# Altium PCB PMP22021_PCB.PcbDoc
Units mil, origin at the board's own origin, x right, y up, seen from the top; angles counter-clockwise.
Board outline 2283.46 x 1181.1 mil, 2 copper layers (Top Layer, Bottom Layer), stack 62 mil thick; 38 components, 23 nets, 108 pads, 31 vias.
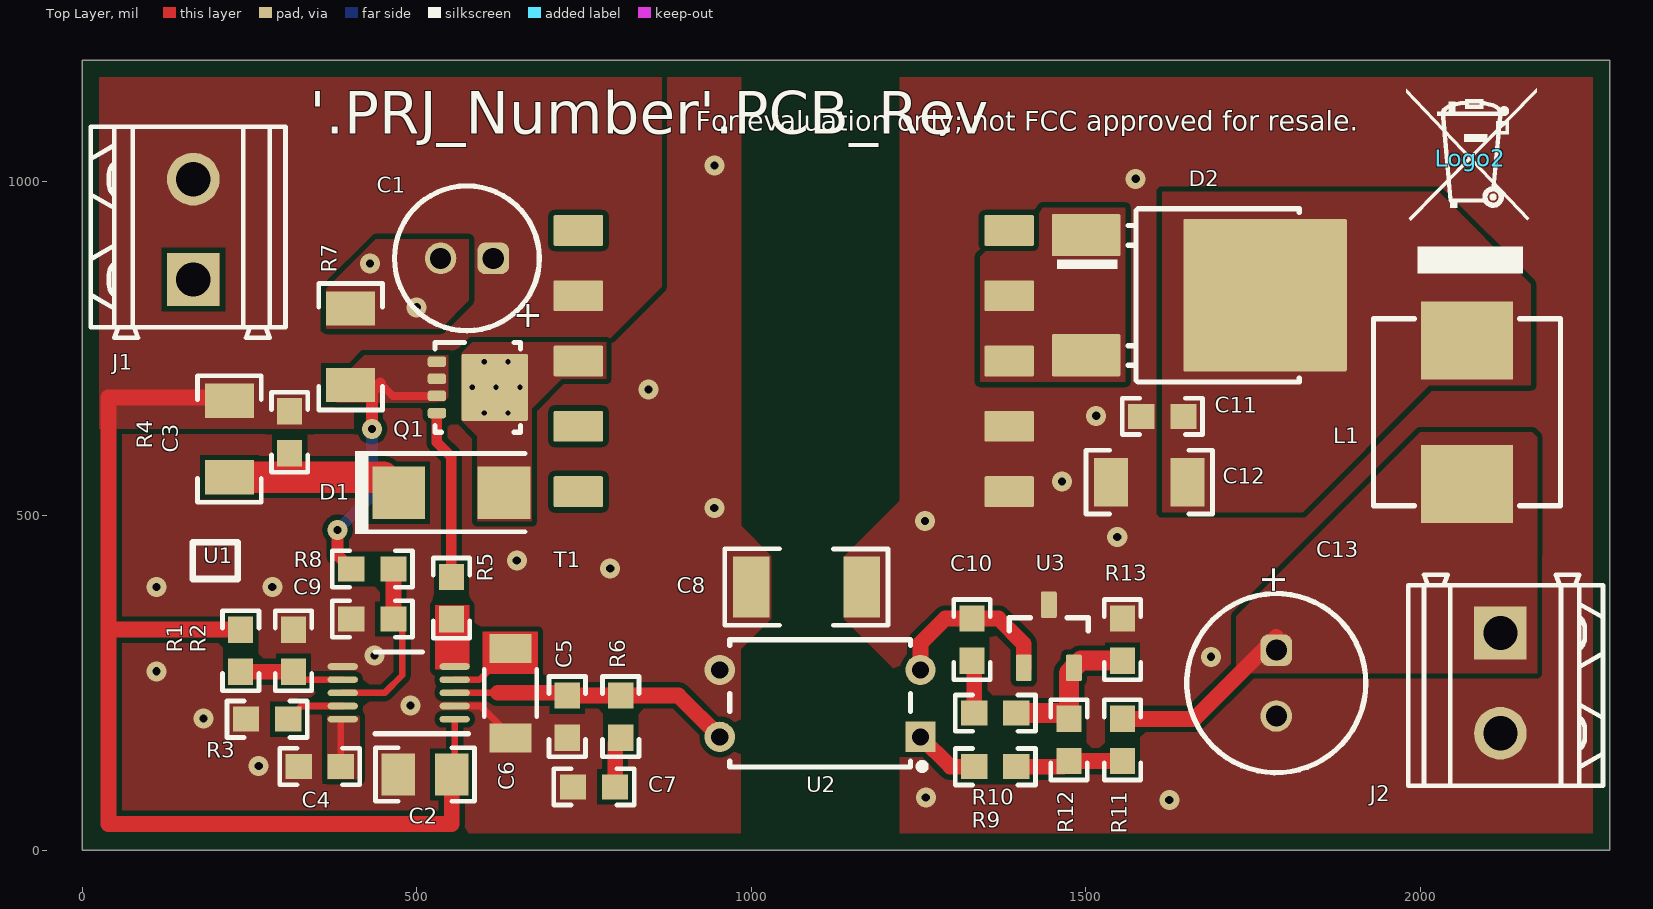
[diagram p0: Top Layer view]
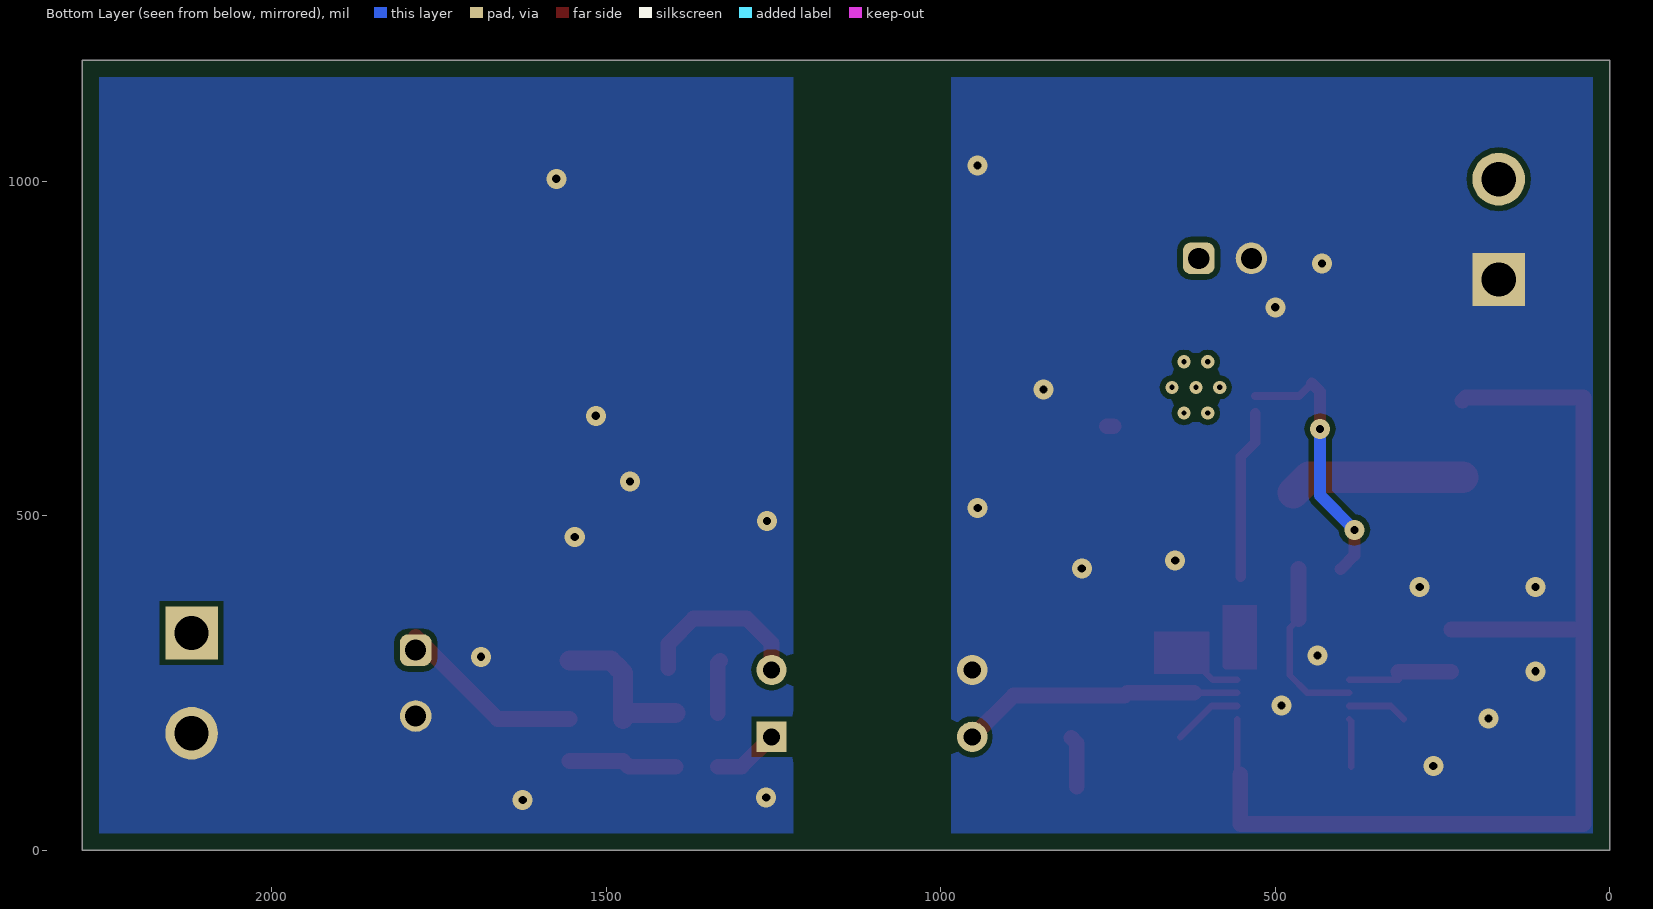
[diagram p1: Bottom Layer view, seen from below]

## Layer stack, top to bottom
Top Solder: solder mask 0.4, Solder Resist, Dk 3.5
Top Layer: signal copper 1.4
Dielectric1: core 59.2, FR-4, Dk 4.8
Bottom Layer: signal copper 1.4
Bottom Solder: solder mask 0.4, Solder Resist, Dk 3.5

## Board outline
0,0 2283.46,0 2283.46,1181.1 0,1181.1

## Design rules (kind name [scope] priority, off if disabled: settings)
AcuteAngle [All] p1: minimum=4.50000000000000E+0001 checktracksonly=FALSE
AssemblyTestPointUsage [All] p1: valid=2
BoardOutlineClearance BoardOutlineClearance_MountingHoles [OnCopper and InComponentClass('Mounting Holes')] p1: gap=25 ignorepadtopadclearanceinfootprint=FALSE
BoardOutlineClearance BoardOutlineClearance_Poly [OnCopper and InPoly] p2: gap=25 ignorepadtopadclearanceinfootprint=FALSE
BoardOutlineClearance [OnCopper and Not InComponentClass('Logo') and not InComponentClass('FiducialMark') and not InRegion(1000,500,4000,800)] p3: gap=25 ignorepadtopadclearanceinfootprint=FALSE
Clearance Clearance_Keepouts [((IsTrack Or IsArc) And Not InPoly) And IsFree and IsKeepOut vs ((IsTrack Or IsArc) And Not InPoly) And IsFree and IsKeepOut] p1: gap=0 ignorepadtopadclearanceinfootprint=FALSE
Clearance Clearance_Poly [InPolygon] p2: gap=8 ignorepadtopadclearanceinfootprint=FALSE except(0: Arc-Hole Track-Hole SMDPad-Hole THPad-Hole Via-Hole Fill-Hole Poly-Hole Region-Hole Text-Hole)
Clearance [All] p3: gap=7.87 ignorepadtopadclearanceinfootprint=FALSE except(0: Arc-Hole Track-Hole SMDPad-Hole THPad-Hole Via-Hole Fill-Hole Poly-Hole Region-Hole Text-Hole)
ComponentClearance ComponentClearance_MountingHoles_FiducialMarks [InComponentClass('Mounting Holes') vs InComponentClass('FiducialMark')] p1: gap=50 collisioncheckmode=3 verticalgap=10 showdistances=FALSE
ComponentClearance ComponentClearance_Shunt [InComponentClass('Header') vs InComponentClass('Shunt')] p2: gap=0 collisioncheckmode=3 verticalgap=0 showdistances=FALSE
ComponentClearance ComponentClearance_Logo [InComponentClass('Logo')] p3: gap=50 collisioncheckmode=3 verticalgap=10 showdistances=FALSE
ComponentClearance ComponentClearance_ScrewToNut [(HasFootprint('NY PMS 440 0025 PH')) vs (HasFootprint('Keystone_1902C'))] p4: gap=5 collisioncheckmode=3 verticalgap=10 showdistances=FALSE
ComponentClearance ComponentClearance_MountingHoles [InComponentClass('Mounting Holes')] p5: gap=250 collisioncheckmode=3 verticalgap=100000 showdistances=FALSE
ComponentClearance ComponentClearance_SmallPassives [HasFootprint('0201*') or HasFootprint('0402*') or HasFootprint('0508') or HasFootprint('0603*') or HasFootprint('0612') or HasFootprint('0805*') or HasFootprint('0815*') or HasFootprint('0830*') or HasFootprint('1206*') or HasFootprint('1210*') or HasFootprint('1808*') or HasFootprint('1812*') or HasFootprint('1825*') or HasFootprint('2010*') or HasFootprint('2220*') or HasFootprint('2225*') or HasFootprint('2512*') or HasFootprint('2728*') or HasFootprint('3518*') vs HasFootprint('0201*') or HasFootprint('0402*') or HasFootprint('0508') or HasFootprint('0603*') or HasFootprint('0612') or HasFootprint('0805*') or HasFootprint('0815*') or HasFootprint('0830*') or HasFootprint('1206*') or HasFootprint('1210*') or HasFootprint('1808*') or HasFootprint('1812*') or HasFootprint('1825*') or HasFootprint('2010*') or HasFootprint('2220*') or HasFootprint('2225*') or HasFootprint('2512*') or HasFootprint('2728*') or HasFootprint('3518*')] p6: gap=14.96 collisioncheckmode=3 verticalgap=10 showdistances=FALSE
ComponentClearance ComponentClearance_THtoSMT [IsThruComponent vs IsSMTComponent] p7: gap=15 collisioncheckmode=3 verticalgap=30 showdistances=FALSE
ComponentClearance ComponentClearance_THtoTH [IsThruComponent vs IsThruComponent] p8: gap=15 collisioncheckmode=3 verticalgap=30 showdistances=FALSE
ComponentClearance [All] p9: gap=15 collisioncheckmode=3 verticalgap=10 showdistances=FALSE
DiffPairsRouting [All] p1: maxlimit=100 minlimit=10 mostfreqgap=10 toplayer_minwidth=15 toplayer_maxwidth=15 toplayer_prefwidth=15 bottomlayer_minwidth=15 bottomlayer_maxwidth=15 bottomlayer_prefwidth=15 maxuncoupledlength=1000
FabricationTestPointUsage TestPointUsage [All] p1: valid=2 allowmultiple=FALSE
FabricationTestpoint Testpoint [All] p1: side=3 testpointundercomponent=TRUE minsize=40 maxsize=100 preferedsize=60 minholesize=0 maxholesize=40 preferedholesize=32 testpointgrid=1 allowsidetop=TRUE allowsidebottom=TRUE usegrid=TRUE gridtolerance=0.01
FanoutControl Fanout_LCC [IsLCC] p1: bgadir=Out bgaviamode=Centered fanoutstyle=Auto fanoutdirection=Alternating viagrid=1 // Fanout_LCC (Default Rule)
FanoutControl Fanout_BGA [IsBGA] p2: bgadir=Out bgaviamode=Centered fanoutstyle=Auto fanoutdirection=Alternating viagrid=1 // Fanout_BGA (Default Rule)
FanoutControl Fanout_Default [All] p4: bgadir=Out bgaviamode=Centered fanoutstyle=Auto fanoutdirection=Alternating viagrid=1 // Fanout_Default (Default Rule)
FanoutControl Fanout_Small [(CompPinCount < 5)] p5: bgadir=Out bgaviamode=Centered fanoutstyle=Auto fanoutdirection=OutThenIn viagrid=1 // Fanout_Small (Default Rule)
HoleSize [All] p1: absolutevalues=TRUE maxlimit=251 minlimit=7.87 maxpercent=80.000 minpercent=20.000
MinimumAnnularRing MinimumAnnularRing_ThermalPadVias [IsVia and InAnyComponent] p1: minimumring=5.91
MinimumAnnularRing [All] p2: minimumring=8
MinimumSolderMaskSliver MinimumSolderMaskSliver_Logo [InComponentClass('Logo') vs InComponentClass('Logo')] p1: minsoldermaskwidth=0.7
MinimumSolderMaskSliver [All] p2: minsoldermaskwidth=3.94
PlaneConnect [All] p1: planeconnectstyle=Direct reliefexpansion=10 reliefentries=4 reliefconductorwidth=10 reliefairgap=10
PolygonConnect [All] p1: connectstyle=Direct reliefconductorwidth=10 reliefentries=4 polygonreliefangle="90 Angle" airgapwidth=10
RoutingVias ThermalPadVias [IsVia and InAnyComponent] p1: holewidth=7.87 width=19.68 viastyle="Through Hole" minholewidth=7.87 minwidth=19.68 maxholewidth=12.99 maxwidth=23.62
RoutingVias [All] p2: holewidth=16 width=34 viastyle="Through Hole" minholewidth=7.87 minwidth=26 maxholewidth=40 maxwidth=65
SilkToBoardRegionClearance [Not ((IsComment or IsDesignator) And (Hide <> 'False')) and not InRegion(1000,500,4000,800)] p1:
SilkToSilkClearance SilkToSilkClearance_Pb-FreeLogo [(HasFootprint('Pb-Free_Overlay_Medium') OR HasFootprint('Pb-Free_Overlay_Small')) vs (HasFootprint('Pb-Free_Overlay_Medium') OR HasFootprint('Pb-Free_Overlay_Small'))] p1: silktosilkclearance=0
SilkToSilkClearance [All] p2: silktosilkclearance=4
SilkToSolderMaskClearance SilkToComponentPadClearance [IsPad and InAnycomponent] p1: minsilkscreentomaskgap=5 clearancetoexposedcopper=TRUE
SilkToSolderMaskClearance "Silk to Solder Mask Opening" [All] p2: minsilkscreentomaskgap=4 clearancetoexposedcopper=FALSE
SolderMaskExpansion [All] p1: expansion=1.97
Width [All] p1: maxlimit=100 minlimit=6 preferedwidth=10 checkconnectedcopper=TRUE
15 further rules are at their usual default settings.

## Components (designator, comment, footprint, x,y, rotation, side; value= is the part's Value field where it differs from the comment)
C1 "860020472003" WCAP-ATG5_500x1100 575,885 r180 top value=10uF
C2 "GRM219R71E105KA88D" 0805_HV 512.44,113.39 r180 top value=1uF
C3 "GRM188R71H273KA61D" 0603 310,625 r270 top value=0.027uF
C4 "GCM188R71H103KA37D" 0603 354.96,125.2 r0 top value=0.01uF
C5 "GRM188R71E104KA01D" 0603 725,200 r90 top value=0.1uF
C6 "GRM31CR71E106KA12L" 1206_180 640,235 r270 top value=10uF
C7 "GRM188R71E105KA12D" 0603 765,95 r180 top value=1uF
C8 "GR442QR73D102KW01L" 1808 1082.68,393.7 r180 top value=1000pF
C9 "06033C101KAT2A" 0603 433.7,345.67 r0 top value=100pF
C10 "GRM188R71C333KA01D" 0603 1330,315 r270 top value=0.033uF
C11 "GRM188R71E105KA12D" 0603 1614.8,648.82 r180 top value=1uF
C12 "C3216X7R1A106K085AC" 1206 1595.12,550.39 r180 top value=10uF
C13 "860010273010" WCAP-ATG8_630x1100 1785,250 r270 top value=330uF
D1 "MURA110T3G" SMA 551.81,534.65 r0 top value=100V
D2 "MBRD1035CTLT4G" DPAK 1634.49,829.92 r0 top value=35V
J1 "691214310002" Wurth_691214310002 165.98,928.35 r90 top
J2 "691214310002" Wurth_691214310002 2120,250 r270 top
L1 "74437349022" WE-LHMI_7050 2070,655 r270 top value=2.2uH
Logo1 "FCC disclaimer" FCC_disclaimer 2870,1255 r0 top
Logo2 "WEEE logo" WEEE_Minimum 2075,1035 r0 top
Q1 "CSD18543Q3A" DNH0008A 591.18,692.13 r0 top value=60V
R1 "CRCW060321K0FKEA" 0603 236.85,298.43 r90 top value=21.0k
R2 "CRCW06034K87FKEA" 0603 315.59,298.43 r270 top value=4.87k
R3 "CRCW060384K5FKEA" 0603 276.22,196.06 r180 top value=84.5k
R4 "CRCW12062K00JNEA" 1206 220,615 r90 top value=2.0k
R5 "CRCW06032R20JNEA" 0603 551.81,377.17 r90 top value=2.2
R6 "CRCW0603499RFKEA" 0603 805,200 r90 top value=499
R7 "CSR1206FKR300" 1206 401.1,752.8 r270 top value=0.3
R8 "CRCW0603200RJNEA" 0603 433.7,420.47 r0 top value=200
R9 "CRCW0603511RFKEA" 0603 1365,125 r0 top value=511
R10 "CRCW06034K42FKEA" 0603 1365,205 r0 top value=4.42k
R11 "CRCW06030000Z0EA" 0603 1555,165 r90 top value=0
R12 "CRCW060314K3FKEA" 0603 1475,165 r270 top value=14.3k
R13 "CRCW060342K2FKEA" 0603 1555,315 r270 top value=42.2k
T1 "750310035" FP-750310035_SMT_17MM75_13MM46-MFG 1063.62,731.5 r0 top
U1 "LM5022QDGSRQ1" DGS0010A_L 473.07,235.43 r180 top
U2 "VO618A-3" DIP-4 1102.99,219.69 r180 top
U3 "ATL431AIDBZR" DBZ0003A_N 1445,320 r90 top

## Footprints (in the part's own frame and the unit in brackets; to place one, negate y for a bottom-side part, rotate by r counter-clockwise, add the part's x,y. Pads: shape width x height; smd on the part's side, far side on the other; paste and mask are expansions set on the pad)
0603 [mm] "0603 from SM-752 data"
  rect 1x0.95 smd: 1(-0.8,0) 2(0.8,0)
  silkscreen extent -1.52,-0.69 1.52,0.69, body extent -0.87,-0.47 0.87,0.47, height 1
0805_HV [mil] "0805 with 30mil clearance between pads"
  rect 50x63 smd: 1(-40,0) 2(40,0)
  silkscreen extent -74,-40 74,40, body extent -43,-29 43,29, height 57
1206 [mm] "1206 from SM-752 data"
  rect 1.3x1.85 smd: 1(-1.45,0) 2(1.45,0)
  silkscreen extent -2.4,-1.21 2.4,1.21, body extent -1.7,-0.9 1.7,0.9, height 1.35
1206_180 [mm] "1206_180"
  rect 1.1x1.6 smd: 1(-1.7,0) 2(1.7,0)
  silkscreen extent -0.9,-1 0.9,1, body extent -1.75,-0.95 1.75,0.95, height 1.8
1808 [mm] "Chip Capacitor, Body 4.6x2.0mm, IPC Medium Density"
  rect 1.4x2.3 smd: 1(-2.1,0) 2(2.1,0)
  silkscreen extent -3.1,-1.45 3.1,1.45, body extent -2.47,-1.2 2.47,1.2, height 2.03
DBZ0003A_N [mm] "SOT23, 3-Leads, Body 2.9x1.3mm, Pitch 0.95mm, Lead Span 2.4mm, IPC Medium Density"
  rrect17% 1x0.6 smd: 1(-1.2,0.95) 2(-1.2,-0.95) 3(1.2,0)
  silkscreen extent 0.2,-1.5 0.7,1.5, body extent -1.26,-1.46 1.26,1.46, height 0.98
DGS0010A_L [mm] "TSSOP, 10-Leads, Body 3x3mm, Pitch 0.5mm, IPC High Density"
  oval 1.15x0.25 smd: 1(-2.125,1) 2(-2.125,0.5) 3(-2.125,0) 4(-2.125,-0.5) 5(-2.125,-1) 6(2.125,-1) 7(2.125,-0.5) 8(2.125,0) 9(2.125,0.5) 10(2.125,1)
  silkscreen extent -2.65,-1.55 0.9,1.55, body extent -2.45,-1.5 2.45,1.5, height 0.96
DIP-4 [mm] "DIP, 4-Leads, Body 6.86x4.83mm, Pitch 2.54mm"
  rect 1.15x1.15 hole 0.65: 1(-3.81,1.27)
  round 1.15 hole 0.65: 2(-3.81,-1.27) 3(3.81,-1.27) 4(3.81,1.27)
  silkscreen extent -4,-2.41 3.43,2.52, body extent -4.02,-2.41 4.02,2.41, height 5.59
DNH0008A [mm] "8 pin VSONP, 0.65 mm pitch"
  rrect50% 0.7x0.4 smd paste-0.05 mask-0.05: 1(-1.55,0.975) 2(-1.55,0.325) 3(-1.55,-0.325) 4(-1.55,-0.975) 5(1.55,-0.975) 6(1.55,-0.325) 7(1.55,0.325) 8(1.55,0.975)
  rrect14% 0.705x1.125 on Top Paste: 9(-0.208,-0.663) 9(-0.208,0.662) 9(0.697,-0.663) 9(0.697,0.662)
  rrect6% 1.775x2.45 on Top Solder: 9(0.327,0)
  rrect4% 2.51x2.55 smd paste-1.5 mask-1.5: 9(0.645,0)
  rect 0.5x0.3 on Top Solder: 9(1.175,-0.975) 9(1.175,-0.325) 9(1.175,0.325) 9(1.175,0.975)
  silkscreen extent -1.62,-1.7 1.62,1.7, body extent -1.65,-1.65 1.65,1.66, height 0.91
DPAK [mm] "D-PAK, 3-Pads, Body 6.22x6.73mm (max), TO-252AA using nominal STEP model"
  rrect6% 2.6x1.6 smd: 1(-3.4,2.28) 3(-3.4,-2.28)
  rrect2% 6.2x5.8 smd paste-2.9: 4(3.4,0)
  silkscreen extent -4.5,-3.3 4.7,3.28, body extent -3.86,-3.29 5.84,3.29, height 2.48
FCC_disclaimer [mil]
FP-750310035_SMT_17MM75_13MM46-MFG [mm]
  rrect9% 1.88x1.17 smd paste+0 mask+0: 1(-8.18,-4.96) 2(-8.18,-2.48) 3(-8.18,0) 4(-8.18,2.48) 5(-8.18,4.96) 6(8.18,4.96) 7(8.18,2.48) 8(8.18,0) 9(8.18,-2.48) 10(8.18,-4.96)
  body extent -9.22,-6.83 9.22,6.83, height 0.25
SMA [mm] "Molded Diode, 2-Leads, Body 4.3x2.6mm, IPC Medium Density, based on OnSemi component dimensions and land pattern"
  rect 2x2 smd: 1(-2,0) 2(2,0)
  silkscreen extent -3.66,-1.57 2.79,1.57, body extent -2.6,-1.3 2.6,1.3, height 2.42
WCAP-ATG5_500x1100 [mm] "TH, 2-Leads, Dia 5mm, Pin Spacing 2mm"
  rrect50% 1.2x1.2 hole 0.8: 1(-1,0)
  round 1.2 hole 0.8: 2(1,0)
  silkscreen extent -2.75,-2.75 2.75,2.75, body extent -2.5,-2.5 2.49,2.5, height 11.11
WCAP-ATG8_630x1100 [mm] "TH, 2-Leads, Dia 6.3mm, Pin Spacing 2.5mm"
  rrect50% 1.2x1.2 hole 0.8: 1(-1.25,0)
  round 1.2 hole 0.8: 2(1.25,0)
  silkscreen extent -3.4,-3.4 3.4,3.4, body extent -3.15,-3.15 3.14,3.15, height 11.11
WE-LHMI_7050 [mm] "Wurth"
  rect 2.95x3.5 smd: 1(-2.725,0) 2(2.725,0)
  silkscreen extent -3.55,-3.55 3.55,3.55, body extent -3.8,-3.45 3.8,3.45, height 5
WEEE_Minimum [mil] "WEEElie bin"
  silkscreen extent -95,-172 99,104
Wurth_691214310002 [mm] "WE"
  rect 2x2 hole 1.3: 1(-1.905,0)
  round 2 hole 1.3: 2(1.905,0)
  silkscreen extent -4.12,-3.5 3.9,3.9, body extent -4.12,-3.5 3.9,3.9, height 8.52

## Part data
C1: library part CMP-0860288-1, "CAP, AL, 10 µF, 25 V, +/- 20%, TH", Cap_Case=5x11mm, Manufacturer="Wurth Elektronik", Tolerance_%=20%, Value2=25V, ValueDisplayed=10µF
C2: library part CMP-0008217-2, "CAP, CERM, 1 uF, 25 V, +/- 10%, X7R, 0805", Cap_Case=0805, Manufacturer=MuRata, Supplier Part Number 1=GRM219R71E105KA88D-ND, TempCo=X7R, Tolerance_%=10%, Value1=Unknown, Value2=25V, ValueDisplayed=1uF
C3: library part CMP-0007448-4, "CAP, CERM, 0.027 uF, 50 V, +/- 10%, X7R, 0603", Cap_Case=0603, Manufacturer=MuRata, Supplier Part Number 1=81-GRM188R71H273KA61, TempCo=X7R, Tolerance_%=10%, Value1=Unknown, Value2=50V, ValueDisplayed=0.027uF
C4: library part CMP-0007143-4, "CAP, CERM, 0.01 uF, 50 V, +/- 10%, X7R, AEC-Q200 Grade 1, 0603", Cap_Case=0603, Manufacturer=MuRata, Supplier Part Number 1=490-4778-1-ND, TempCo=X7R, Tolerance_%=10%, Value1=Unknown, Value2=50V, ValueDisplayed=0.01uF
C5: library part CMP-0007404-4, "CAP, CERM, 0.1 uF, 25 V, +/- 10%, X7R, 0603", Cap_Case=0603, Manufacturer=MuRata, Supplier Part Number 1=490-1524-1-ND, TempCo=X7R, Tolerance_%=10%, Value1=Unknown, Value2=25V, ValueDisplayed=0.1uF
C6: library part CMP-0008965-2, "CAP, CERM, 10 uF, 25 V, +/- 10%, X7R, 1206", Cap_Case=2220, Manufacturer=MuRata, Supplier Part Number 1=81-GRM31CR71E106KA12, TempCo=X7R, Tolerance_%=10%, Value1=Unknown, Value2=25V, ValueDisplayed=10uF
C7 C11: library part CMP-0007405-4, "CAP, CERM, 1 uF, 25 V, +/- 10%, X7R, 0603", Cap_Case=0603, Manufacturer=MuRata, Supplier Part Number 1=490-5307-1-ND, TempCo=X7R, Tolerance_%=10%, Value1=Unknown, Value2=25V, ValueDisplayed=1uF
C8: library part CMP-0009436-2, "CAP, CERM, 1000 pF, 2000 V, +/- 10%, X7R, 1808", Cap_Case=1808, Manufacturer=MuRata, Supplier Part Number 1=490-8145-1-ND, TempCo=X7R, Tolerance_%=10%, Value1=Unknown, Value2=2000V, ValueDisplayed=1000pF
C9: library part CMP-0006751-4, "CAP, CERM, 100 pF, 25 V, +/- 10%, X7R, 0603", Cap_Case=0603, Manufacturer=AVX, Supplier Part Number 1=55J3899, TempCo=X7R, Tolerance_%=10%, Value1=Unknown, Value2=25V, ValueDisplayed=100pF
C10: library part CMP-0007392-5, "CAP, CERM, 0.033 uF, 16 V, +/- 10%, X7R, 0603", Cap_Case=0603, Manufacturer=MuRata, Supplier Part Number 1=490-1528-1-ND, TempCo=X7R, Tolerance_%=10%, Value1=Unknown, Value2=16V, ValueDisplayed=0.033uF
C12: library part CMP-0008687-2, "CAP, CERM, 10 uF, 10 V, +/- 10%, X7R, 1206", Cap_Case=1206, Manufacturer=TDK, Supplier Part Number 1=445-14793-1-ND, TempCo=X7R, Tolerance_%=10%, Value1="0.002454 ohm", Value2=10V, ValueDisplayed=10uF
C13: library part CMP-0860287-1, "CAP, AL, 330 µF, 10 V, +/- 20%, TH", Cap_Case=6.3x11mm, Manufacturer="Wurth Elektronik", Tolerance_%=20%, Value2=10V, ValueDisplayed=330µF
D1: library part CMP-0029196-2, "Diode, Ultrafast, 100 V, 2 A, SMA", Manufacturer="ON Semiconductor", Value1=2A, Value2=V
D2: library part CMP-0028474-1, "Diode, Schottky, 35 V, 10 A, DPAK", Manufacturer="ON Semiconductor", Supplier Part Number 1=MBRD1035CTLT4GOSCT-ND, Value1=10A, Value2=0.56V
J1 J2: library part CMP-0054822-2, "Terminal Block, 2x1, 3.81mm, 24-16 AWG, 10A, 300VAC, TH", Manufacturer="Wurth Elektronik"
L1: library part CMP-0064106-1, "Inductor, Shielded Drum Core, Powdered Iron, 2.2 uH, 7.5 A, 0.0112 ohm, SMD", Manufacturer="Wurth Elektronik", Supplier Part Number 1=732-3352-1-ND, Value1="0.0112 ohm", Value2=7.5A, ValueDisplayed=2.2uH
Logo1: library part CMP-0074847-1, "FCC_disclaimer"
Logo2: library part CMP-0074769-1
Q1: library part CMP-0000826-1, "MOSFET, N-CH, 60 V, 35 A, DNH0008A (VSONP-8)", Alternate Manufacturer=None, Manufacturer="Texas Instruments", Supplier Part Number 1=CSD18543Q3A-ND, Value1=0.01, Value2="11.1 nC"
R1: library part CMP-0022212-4, "RES, 21.0 k, 1%, 0.1 W, AEC-Q200 Grade 0, 0603", Manufacturer=Vishay-Dale, Power_W=100mW, Supplier Part Number 1=541-21.0KHCT-ND, TempCo="100 ppm/C", Tolerance_%=1%, Value2=0.1W, Value_Code=21k0, ValueDisplayed=21.0k
R2: library part CMP-0022457-4, "RES, 4.87 k, 1%, 0.1 W, AEC-Q200 Grade 0, 0603", Manufacturer=Vishay-Dale, Power_W=100mW, Supplier Part Number 1=541-4.87KHCT-ND, TempCo="100 ppm/C", Tolerance_%=1%, Value2=0.1W, Value_Code=4k87, ValueDisplayed=4.87k
R3: library part CMP-0022624-4, "RES, 84.5 k, 1%, 0.1 W, AEC-Q200 Grade 0, 0603", Manufacturer=Vishay-Dale, Power_W=100mW, Supplier Part Number 1=541-84.5KHCT-ND, TempCo="100 ppm/C", Tolerance_%=1%, Value2=0.1W, Value_Code=84k5, ValueDisplayed=84.5k
R4: library part CMP-0018640-3, "RES, 2.0 k, 5%, 0.25 W, AEC-Q200 Grade 0, 1206", Manufacturer=Vishay-Dale, Power_W=250mW, Supplier Part Number 1=541-2.0KECT-ND, TempCo="200 ppm/C", Tolerance_%=5%, Value2=0.25W, Value_Code=2k00, ValueDisplayed=2.0k
R5: library part CMP-0025777-4, "RES, 2.2, 5%, 0.1 W, AEC-Q200 Grade 0, 0603", Manufacturer=Vishay-Dale, Power_W=100mW, Supplier Part Number 1=541-2.2GCT-ND, TempCo="200 ppm/C", Tolerance_%=5%, Value2=0.1W, Value_Code=2R20, ValueDisplayed=2.2
R6: library part CMP-0022446-5, "RES, 499, 1%, 0.1 W, AEC-Q200 Grade 0, 0603", Manufacturer=Vishay-Dale, Power_W=100mW, Supplier Part Number 1=541-499HCT-ND, TempCo="100 ppm/C", Tolerance_%=1%, Value2=0.1W, Value_Code=499R, ValueDisplayed=499
R7: library part CMP-0017268-2, "RES, 0.3, 1%, 0.5 W, 1206", Manufacturer="Stackpole Electronics Inc", Power_W=500mW, Supplier Part Number 1=CSR1206FKR300CT-ND, TempCo="100 ppm/C", Tolerance_%=1%, Value2=0.5W, Value_Code=R300, ValueDisplayed=0.3
R8: library part CMP-0025752-4, "RES, 200, 5%, 0.1 W, AEC-Q200 Grade 0, 0603", Manufacturer=Vishay-Dale, Power_W=100mW, Supplier Part Number 1=541-200GCT-ND, TempCo="200 ppm/C", Tolerance_%=5%, Value2=0.1W, Value_Code=200R, ValueDisplayed=200
R9: library part CMP-0022481-5, "RES, 511, 1%, 0.1 W, AEC-Q200 Grade 0, 0603", Manufacturer=Vishay-Dale, Power_W=100mW, Supplier Part Number 1=541-511HCT-ND, TempCo="100 ppm/C", Tolerance_%=1%, Value2=0.1W, Value_Code=511R, ValueDisplayed=511
R10: library part CMP-0022453-4, "RES, 4.42 k, 1%, 0.1 W, AEC-Q200 Grade 0, 0603", Manufacturer=Vishay-Dale, Power_W=100mW, Supplier Part Number 1=541-4.42KHCT-ND, TempCo="100 ppm/C", Tolerance_%=1%, Value2=0.1W, Value_Code=4k42, ValueDisplayed=4.42k
R11: library part CMP-0025697-4, "RES, 0, 5%, 0.1 W, AEC-Q200 Grade 0, 0603", Manufacturer=Vishay-Dale, Power_W=100mW, Supplier Part Number 1=541-0.0GCT-ND, TempCo="200 ppm/C", Tolerance_%=5%, Value2=0.1W, Value_Code=0000, ValueDisplayed=0
R12: library part CMP-0022055-4, "RES, 14.3 k, 1%, 0.1 W, AEC-Q200 Grade 0, 0603", Manufacturer=Vishay-Dale, Power_W=100mW, Supplier Part Number 1=541-14.3KHCT-ND, TempCo="100 ppm/C", Tolerance_%=1%, Value2=0.1W, Value_Code=14k3, ValueDisplayed=14.3k
R13: library part CMP-0022418-4, "RES, 42.2 k, 1%, 0.1 W, AEC-Q200 Grade 0, 0603", Manufacturer=Vishay-Dale, Power_W=100mW, Supplier Part Number 1=541-42.2KHCT-ND, TempCo="100 ppm/C", Tolerance_%=1%, Value2=0.1W, Value_Code=42k2, ValueDisplayed=42.2k
T1: library part CMP-0087256-1, "MID-POE Power Over Ethernet Transformer", Manufacturer="Wurth Electronik"
U1: library part CMP-0076391-1, "2.2MHz 60-V Low Side Controller for Boost, SEPIC and Flyback, DGS0010A (VSSOP-10)", Alternate Manufacturer="Texas Instruments", Alternate PartNumber=LM5022QDGSTQ1
U2: library part CMP-0083653-1, "Optocoupler, 5.3 kV, 100-200% CTR, SMT", Manufacturer=Vishay-Semiconductor, Supplier Part Number 1=VO618A-3-ND, Voltage_Isolation_Vrms=5.3kV
U3: library part CMP-0066199-1, "2.5V Low Iq Adjustable Precision Shunt Regulator, DBZ0003A (SOT-23-3)", Alternate Manufacturer="Texas Instruments"

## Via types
v1: diameter 29.92, hole 12.2, Top Layer to Bottom Layer, 21 vias
v2: diameter 19.68, hole 7.87, Top Layer to Bottom Layer, 7 vias
v3: diameter 29.92, hole 12.2, Top Layer to Bottom Layer, tented both sides, 3 vias

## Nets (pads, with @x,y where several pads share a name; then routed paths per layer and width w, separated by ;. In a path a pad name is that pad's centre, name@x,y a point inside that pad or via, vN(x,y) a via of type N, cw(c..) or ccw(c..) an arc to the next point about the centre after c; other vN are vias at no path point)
COMP: C5.2 R6.2 U1.3 U2.4 | length 423.5
  Top Layer w10: U1.3 621.06,235.43
  Top Layer w23: 621.06,235.43 721.06,235.43 C5.2
  Top Layer w23.62: C5.2 R6.2 891.18,231.5 U2.4
CS: C9.2 R8.2 U1.8 | length 264
  Top Layer w9.84: U1.8 451.97,235.43 478.39,261.85 478.39,332.48 C9.2
  Top Layer w23.62: C9.2 R8.2
NetC1_1: C1.1 C2.1 C3.1 J1.2 R1.2 R4.2 T1.4 U1.1 | length 1689.2
  Top Layer w9.84: C2.1 556.73,117.68 U1.1
  Top Layer w23.62: R4.2 215.2,676.89 39.37,676.89 39.37,329.92 ; R1.2 39.37,329.92 ; C2.1 552.44,39.37 39.37,39.37 39.37,329.92
NetC3_2: C3.2 D1.1 R4.1 | length 262.7
  Top Layer w47.24: R4.1 449.8,557.91 D1.1
NetC4_2: C4.2 U1.10 | length 72.1
  Top Layer w9.84: C4.2 386.46,193.11 U1.10
NetC6_1: C6.1 U1.4 | length 104.9
  Top Layer w9.84: U1.4 593.7,255.12 C6.1@641.73,303.15
NetC7_1: C7.1 R6.1 | length 77
  Top Layer w23: C7.1 796.5,160 R6.1
NetC10_1: C10.1 U2.2 U3.1 | length 261.2
  Top Layer w23.62: U2.2 1252.99,309.49 1290,346.5 C10.1 1369.61,346.5 1407.6,308.5 U3.1
NetC10_2: C10.2 R10.1 | length 80
  Top Layer w23: C10.2 1333.5,280 R10.1
NetC11_1: C11.1 C12.1 D2.4 L1.1
NetD1_2: D1.2 Q1.5 Q1.6 Q1.7 Q1.8 Q1.9@616.57,692.13 T1.3
  other v2: 600.83,653.74 636.46,653.74 583.01,692.13 618.64,692.13 654.27,692.13 600.83,730.51 636.46,730.51
NetD2_1: D2.1 D2.3 T1.7 T1.8
NetQ1_1: Q1.1 Q1.2 Q1.3 R7.2 R8.1 | length 404.9
  Top Layer w11.81: 445.51,698.03 464.21,679.33 Q1.3
  Top Layer w17.72: v1(381.66,479.04) 381.66,441.02 R8.1 ; v1(433.07,629.92) 433.07,685.59 445.51,698.03
  Bottom Layer w17.72: v1(381.66,479.04) 433.07,530.45 v1(433.07,629.92)
NetQ1_4: Q1.4 R5.2 | length 254
  Top Layer w15.75: Q1.4 530.16,610.23 551.81,588.58 R5.2
NetR1_1: R1.1 R2.2 U1.7 | length 152.6
  Top Layer w9.84: R2.2@315.59,255.12 U1.7
  Top Layer w23.62: R1.1 R2.2
NetR3_1: R3.1 U1.9 | length 89.8
  Top Layer w9.84: R3.1 327.4,215.75 U1.9
NetR5_1: R5.1 U1.5
NetR9_1: R9.1 U2.1 | length 99
  Top Layer w23: U2.1 1297.68,125 R9.1
NetR9_2: R9.2 R11.1 R12.2 | length 162
  Top Layer w23.62: R9.2 1466.5,125 R12.2 R11.1
NetR10_2: R10.2 R12.1 R13.2 U3.2 | length 238.4
  Top Layer w30: R10.2 1466.5,205 R12.1 1475,265.35 U3.2 1493.15,283.5 R13.2
PGND: C1.2 C2.2 C4.1 C5.1 C6.2 C7.2 C8.2 C9.1 J1.1 R2.1 R3.2 R7.1 U1.2 U1.6 U2.3 | length 104.2
  Top Layer w9.84: U1.2 595.28,215.75 C6.2@641.73,169.29
  other v1: 263.78,125.98 181.1,196.85 490.56,216.54 110.87,267.72 110.87,393.7 284.09,393.77 789.23,421.26 944.88,511.81 846.46,688.98 430,877.37 945.12,1023.62
  other v3: 437.01,291.34 649.61,433.07 500,811.85
SGND: C8.1 C11.2 C12.2 C13.2 J2.2 R13.1 T1.9 T1.10 U3.3
  other v1: 1625,75 1260.99,78.74 1687.64,289.37 1547.24,468.5 1259.84,492.13 1464.57,551.18 1515.75,649.61 1574.8,1003.94
VOUT: C13.1 J2.1 L1.2 R11.2 | length 280.7
  Top Layer w23.62: R11.2 1662.6,196.5 C13.1@1785,318.9
pads on no net: Q1.9@583.01,666.04 Q1.9@583.01,718.21 Q1.9@604.07,692.13 Q1.9@618.64,666.04 Q1.9@618.64,718.21 Q1.9@637.44,653.74 Q1.9@637.44,679.33 Q1.9@637.44,704.92 Q1.9@637.44,730.51 T1.1 T1.2 T1.5 T1.6
copper on no net: | length 10.4
  Top Layer w23.62: 741.57,633.86 751.97,633.86

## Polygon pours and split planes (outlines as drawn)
VOUT on Top Layer "TOP_LAYER_VOUT_P002" (solid, remove dead copper, pour order 2): 2175,625 2000,625 1725,350 1725,265 2174.8,265
PGND on Top Layer "TOP_LAYER_PGND_P032" (solid, remove dead copper, pour order 32): 985,1181.1 0,1181.1 0,0 984.25,0 984.25,300.71 1030,346.46 1030,440 985,485
SGND on Top Layer "TOP_LAYER_SGND_P030" (solid, remove dead copper, pour order 30): 2285,1180 1222.01,1180 1222.01,522.52 1139.33,439.84 1139.33,345.35 1222.01,262.68 1222.01,-1.1 2285,-1.1
NetC11_1 on Top Layer "TOP_LAYER_NETC11_1_P026" (solid, remove dead copper, pour order 26): 1614.17,505.77 1824.67,505.77 2013.9,695 2165.35,695 2165.35,846.46 2027.56,984.25 1614.17,984.25
NetD2_1 on Top Layer "TOP_LAYER_NETD2_1_P020" (solid, remove dead copper, pour order 20): 1342.52,700.79 1559.06,700.79 1559.06,960.63 1342.52,960.63
NetC4_2 on Top Layer "TOP_LAYER_NETC4_2_P004" (solid, remove dead copper, pour order 4): 366.14,201.13 414.03,201.13 414.94,200.21 414.94,106.3 366.14,106.3
NetC1_1 on Top Layer "TOP_LAYER_NETC1_1_P018" (solid, remove dead copper, pour order 18): 0,1181.1 0,629.92 405.51,629.92 405.51,724.41 421.26,740.16 763.78,740.16 866.14,842.52 866.14,1181.1
NetD1_2 on Top Layer "TOP_LAYER_NETD1_2_P014" (solid, remove dead copper, pour order 14): 783.46,759.84 582.68,759.84 566.93,744.09 566.93,642.52 590.55,618.9 590.55,492.13 671.89,492.13 671.89,660.08 716.54,704.72 783.46,704.72
NetQ1_1 on Top Layer "TOP_LAYER_NETQ1_1_P008" (solid, remove dead copper, pour order 8): 380.54,669.29 547.24,669.29 547.24,740.16 421.26,740.16 380.54,699.44
PGND on Top Layer "TOP_LAYER_PGND_P006" (solid, remove dead copper, pour order 6): 365.69,779.53 535.08,779.53 577.78,822.23 577.78,913.39 438.9,913.39 365.69,840.18
SGND on Bottom Layer "BOTTOM_LAYER_SGND_P028" (solid, remove dead copper, pour order 28): 1220.47,1155.61 2257.98,1155.61 2257.98,25.49 1220.47,25.49
PGND on Bottom Layer "BOTTOM_LAYER_PGND_P010" (solid, remove dead copper, pour order 10): 0,1181.1 984.25,1181.1 984.25,0 0,0

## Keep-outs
Keep-Out Layer:
  text ".Layer_Name" at 577,-858.49 h60

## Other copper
Top Layer:
  region net NetC6_1: 598.43,326.77 598.43,263.78 681.1,263.78 681.1,326.77
  region net NetR5_1: 527.56,366.14 578.74,366.14 578.74,273.62 574.8,269.69 573.62,270.87 527.56,270.87
  text ".Layer_Name" at 577,-858.49 h60
Bottom Layer:
  text ".Layer_Name" at 577,-858.49 h60

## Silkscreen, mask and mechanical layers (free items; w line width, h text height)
Top Overlay:
  lines w10: 165.35,405.51 165.35,460.63 232.28,460.63 232.28,405.51 165.35,405.51
  text "'.PRJ_Number'.PCB_Rev" at 340,1050 h108.27
  text ".Layer_Name" at 577,-858.49 h60
Bottom Overlay:
  text ".Layer_Name" at 577,-858.49 h60
Top Paste:
  text ".Layer_Name" at 577,-858.49 h60
Bottom Paste:
  text ".Layer_Name" at 577,-858.49 h60
Top Solder:
  text ".Layer_Name" at 577,-858.49 h60
  text ".Layer_Name" at 577,-858.49 h60
Bottom Solder:
  text ".Layer_Name" at 577,-858.49 h60
Drill Guide:
  text ".Layer_Name" at 577,-858.49 h60
M1 Board Outline:
  the board outline again, w10
  text ".Layer_Name" at 577,-858.49 h60
M2 Board Dimensions:
  rectangle: 0,-275 125,-150
  rectangle: 125,-400 500,-275
  lines w7: 0,-275 1000,-275 ; 125,-400 125,-150 ; 250,-400 250,-150 ; 500,-400 500,-150 ; 750,-400 750,-150 ; 0,-400 1000,-400 1000,-150 0,-150 0,-400
  text ".Layer_Name" at 577,-858.49 h60
M3 3D STEP Top:
  text ".Layer_Name" at 577,-858.49 h60
M4 3D STEP Bottom:
  text ".Layer_Name" at 577,-858.49 h60
M5 Assembly Top:
  lines w10: -292,-930.17 6308,-930.17 ; -292,-726.83 6310,-726.83 ; -292,-523.5 -292,-1133.5 3713,-1133.5 6310,-1133.5 6310,-523.5 -291.5,-523.5 -291.5,-1133.5 1284,-1133.5 ; 2173,-1133.5 2173,-523.5 ; 3440,-726.83 3440,-523.5 ; 4280,-726.83 4280,-523.5 ; 4902,-1140 4902,-937.17
  text "COMPONENTS MARKED 'DNP' SHOULD NOT BE POPULATED." at 1153.5,-318.5 h60
  text "ASSEMBLY VARIANT:" at 1153,-434 h60
  text ".VariantName" at 2189,-434 h60
  text "PCB VIEWED FROM TOP SIDE" at -228.5,-655.67 h60
  text "BOARD #:" at 2248,-655.67 h60
  text ".PRJ_Number" at 2793.5,-655.67 h60
  text "REV:" at 3638,-655.67 h60
  text ".PCB_Rev" at 3929.5,-655.67 h60
  text "SVN REV:" at 4476,-655.67 h60
  text ".VersionControl_RevNumber" at 4982,-655.67 h60
  text "TID #:" at 2248,-859 h60
  text ".TID" at 2793.5,-859 h60
  text "PLOT NAME =" at -228.5,-1064.34 h60
  text ".plot_File_Name" at 577,-1064.34 h60
  text "GENERATED    :" at 2250,-1064.34 h60
  text ".Print_Date" at 3119.5,-1064.34 h60
  text ".Print_Time" at 3848.5,-1064.34 h60
  text "TEXAS INSTRUMENTS" at 5113,-1064.34 h60
M6 Assembly Bottom:
  lines w10: -292.5,-727.33 6309.5,-727.33 ; -290.5,-930.67 6309.5,-930.67 ; 1115.5,-1140.5 1115.5,-937.67 ; 1737.5,-727.33 1737.5,-524 ; 2577.5,-727.33 2577.5,-524 ; 3844.5,-1134 3844.5,-524 ; 4733.5,-1134 6309,-1134 6309,-524 -292.5,-524 -292.5,-1134 2304.5,-1134 6309.5,-1134 6309.5,-524
  text "COMPONENTS MARKED 'DNP' SHOULD NOT BE POPULATED." at 6102,-318 h60
  text ".VariantName" at 5058,-434 h60
  text "ASSEMBLY VARIANT:" at 6097,-434 h60
  text ".VersionControl_RevNumber" at 1035.5,-656.17 h60
  text "SVN REV:" at 1541.5,-656.17 h60
  text ".PCB_Rev" at 2088,-656.17 h60
  text "REV:" at 2379.5,-656.17 h60
  text ".PRJ_Number" at 3224,-656.17 h60
  text "BOARD #:" at 3769.5,-656.17 h60
  text "PCB VIEWED FROM BOTTOM SIDE" at 6246,-656.17 h60
  text ".TID" at 3224,-859.5 h60
  text "TID #:" at 3769.5,-859.5 h60
  text "TEXAS INSTRUMENTS" at 904.5,-1064.84 h60
  text ".Print_Time" at 2169,-1064.84 h60
  text ".Print_Date" at 2898,-1064.84 h60
  text "GENERATED    :" at 3767.5,-1064.84 h60
  text ".plot_File_Name" at 5440.5,-1064.84 h60
  text "PLOT NAME =" at 6246,-1064.84 h60
M9 Title Sheet:
  drawing of 57 lines, arcs and shapes, not listed
  text "1" at 739.84,8036.5 h70
  text "2" at 3235.5,8036.5 h70
  text "3" at 5724.84,8036.5 h70
  text "4" at 8231.51,8036.5 h70
  text "5" at 10730.5,8036.5 h70
  text "6" at 13235.5,8036.5 h70
  text "A" at -416.5,6893.5 h70
  text "A" at 14383.5,6893.5 h70
  text "B" at -416.5,4513.5 h70
  text "B" at 14383.5,4513.5 h70
  text "C" at -416.5,2138.5 h70
  text "C" at 14383.5,2138.5 h70
  text "PROJECT TITLE:" at 11343.5,277.5 h45
  text ".PRJ_Title" at 11393.5,144.17 h70
  text "DESIGNED FOR:" at 11343.5,-23.5 h45
  text ".PRJ_Customer" at 11393.5,-163.5 h70
  text "D" at -416.5,-231.5 h70
  text "D" at 14383.5,-231.5 h70
  text "FILE NAME:" at 11343.5,-323.5 h45
  text ".PCB_File_Name_No_Path" at 11393.5,-443.5 h70
  text "Texas Instruments (TI) and/or its licensors do not warrant the accuracy or completeness of this specification" at 6374,-605.34 h45
  text "ENGINEER:" at 11343.5,-613.5 h45
  text "LAYOUT BY:" at 12848.5,-613.5 h45
  text "or any information contained therein. TI and/or its licensors do not warrant that this design will meet" at 6329.01,-718 h45
  text ".PRJ_Engineer" at 11393.5,-768.49 h70
  text ".PCB_Layout" at 12899,-768.49 h70
  text "the specifications, will be suitable for your application or fit for any particular purpose, or will operate in" at 6329.01,-830.67 h45
  text ".Layer_Name" at 577,-858.49 h60
  text "ALTIUM DESIGNER VERSION:" at 12848.5,-923.5 h45
  text "an implementation. TI and/or its licensors do not warrant that the design is production worthy. You should" at 6329.01,-943.33 h45
  text "completely validate and test your design implementation to confirm the system functionality for your application." at 6374,-1056 h45
  text ".print_Scale" at 11393.5,-1056.83 h70
  text ".Application_BuildNumber" at 12899,-1056.83 h70
  text "1" at 739.84,-1263.5 h70
  text "2" at 3235.5,-1263.5 h70
  text "3" at 5724.84,-1263.5 h70
  text "4" at 8231.51,-1263.5 h70
  text "5" at 10730.5,-1263.5 h70
  text "6" at 13235.5,-1263.5 h70
M10 Fab Notes:
  drawing of 189 lines, arcs and shapes, not listed
  text "DESIGN INFORMATION" at 12382.02,6356.17 h60
  text "MIN. TRACK WIDTH:" at 11737.46,6224.05 h60
  text "8" at 12833.7,6224.05 h60
  text "MIL" at 12988.46,6224.05 h60
  text "MIN. CLEARANCE:" at 11737.46,6099.92 h60
  text "0.2" at 12773.7,6099.93 h60
  text "mm" at 12988.46,6099.92 h60
  text "MIN. VIA PAD SIZE:" at 11737.46,5975.8 h60
  text "24" at 12803.71,5975.8 h60
  text "MIL" at 12988.46,5975.8 h60
  text "0.05mm (2MIL)" at 12432.46,5845.9 h60
  text "MINIMUM ANNULAR RING" at 11408.23,5837.67 h60
  text "EXTERNAL" at 13140.46,5837.67 h60
  text "PER" at 11608.23,5727.55 h60
  text "IPC-D-275 CLASS 2 LEVEL C" at 11828.23,5727.54 h60
  text "MIL, HOLES" at 13316.46,5627.07 h60
  text "+/-" at 12924,5618.48 h60
  text "+/-" at 13778,5618.48 h60
  text "REGISTRATION TOLERANCES:" at 11408.23,5617.42 h60
  text "METAL" at 12608,5617.42 h60
  text "5" at 13184.2,5617.42 h60
  text "3" at 14017.2,5617.42 h60
  text "MIL" at 14133.46,5617.42 h60
  text "HOLE SIZE TOLERANCE (UNLESS OTHERWISE SPECIFIED):" at 11408.23,5519.1 h60
  text "+/-" at 13778,5516.23 h60
  text "3" at 14017.2,5515.17 h60
  text "MIL" at 14133.46,5515.17 h60
  text "MATERIAL:" at 11333.46,5377.52 h60
  text "FR-4 High Tg" at 12319.9,5249 h60
  text "X" at 12175.46,5241.01 h60
  text "FR-408" at 11754.46,5236.49 h60
  text "OTHER" at 13242.46,5236.49 h60
  text "62 MIL (1.6mm) +/-10%" at 12074.56,5093.46 h60
  text "X" at 11954.46,5091.01 h60
  text "THICKNESS:" at 11408.23,5085.24 h60
  text "OTHER" at 13359.46,5085.24 h60
  text "TOLERANCE:" at 11408.23,4946.92 h60
  text "X" at 12256.46,4946.92 h60
  text "ANSI IPC-6012 TYPE 3 CLASS 2" at 12434.48,4946.92 h60
  text "OTHER +/-" at 12434.46,4802.73 h60
  text "BOW & TWIST:" at 11408.23,4657.54 h60
  text "X" at 12256.46,4657.54 h60
  text "ANSI IPC-6012 TYPE 3 CLASS 2" at 12434.48,4657.54 h60
  text "OTHER +/-" at 12434.46,4510.85 h60
  text "DRILLING:" at 11333.46,4380.23 h60
  text "NC_DRILL FILES" at 13094.46,4275.04 h60
  text "REFERENCE:" at 11408.23,4271.1 h60
  text "X" at 12065.46,4271.01 h60
  text "AS SHOWN" at 12243.46,4271.1 h60
  text "X" at 12966.46,4271.1 h60
  text "OTHER" at 13392.46,4128.85 h60
  text "PTH COPPER THICKNESS:" at 11407.91,4125.32 h60
  text "X" at 12547.14,4125.32 h60
  text "20-30 um" at 12675.14,4125.32 h60
  text "BOARD FINISH:" at 11333.46,3977.73 h60
  text "SILKSCREEN:" at 11488.68,3867.6 h60
  text "X" at 12446.46,3867.6 h60
  text "TOP" at 12563.46,3867.6 h60
  text "X" at 12956.46,3867.6 h60
  text "BOTTOM" at 13074.46,3867.6 h60
  text "SILKSCREEN COLOR:" at 11488.68,3712.41 h60
  text "X" at 12445.46,3712.41 h60
  text "WHITE" at 12563.46,3712.41 h60
  text "OTHER" at 13074.46,3712.41 h60
  text "X" at 12576.46,3568.96 h60
  text "GREEN" at 12694.46,3568.96 h60
  text "OTHER" at 13312.46,3568.96 h60
  text "SOLDER RESIST COLOR:" at 11488.68,3562.1 h60
  text "X" at 12576.46,3414.71 h60
  text "MATTE" at 12694.46,3414.71 h60
  text "SEMI-GLOSS" at 13312,3414.07 h60
  text "IMMERSION GOLD (ENIG)" at 12394.46,3241.94 h60
  text "ENEPIG" at 13732,3234.72 h60
  text "SURFACE FINISH:" at 11333.46,3233.72 h60
  text "X" at 12216.46,3233.72 h60
  text "IMM. TIN/SILVER OR EQUIV" at 11663,3096.4 h60
  text "OTHER" at 13094.46,3092.47 h60
  text "ARRAY/PANEL:" at 11333.46,2937.09 h60
  text "CUT AND TRIM PER M1 BOARD OUTLINE" at 12394.46,2928.87 h60
  text "N.C. ROUTE" at 12394.46,2792.9 h60
  text "X" at 13082.46,2792.9 h60
  text "V. SCORE" at 13260.46,2792.9 h60
  text "CERTIFICATION:" at 11333.46,2663.77 h60
  text "MATERIALS AND WORKMANSHIP FOR ALL PCBS" at 12058.46,2663.77 h60
  text "TO MEET OR EXCEED THE REQUIREMENTS OF:" at 12058.46,2569.71 h60
  text "X" at 11695.97,2441.08 h60
  text "ANSI IPC-A-600F CLASS ->" at 11823.96,2441.08 h60
  text "X" at 13471.97,2441.08 h60
  text "2" at 13581.96,2441.08 h60
  text "1" at 13266.96,2439.58 h60
  text "3" at 13935.96,2439.58 h60
  text "X" at 12507.97,2293.39 h60
  text "RoHS" at 12635.96,2293.39 h60
  text "OTHER" at 13280.36,2293.39 h60
  text "PER ORDER" at 13677.42,2293.39 h60
  text "ALL BOARDS MUST MEET OR EXCEED UL94-V0 REQUIREMENTS." at 11361,2139.57 h60
  text "PCB MUST BEAR THE UL94V-0 UL REGISTERED MATERIAL ID NUMBER" at 11361,2023.5 h60
  text "ADDITIONAL REQUIREMENTS:" at 11333.46,1854.08 h60
  text "MICROSECTION:" at 11408.23,1746.95 h60
  text "YES" at 12313.96,1746.95 h60
  text "REQUIRED" at 13175.46,1602.62 h60
  text "BARE BOARD ELEC. TEST:" at 11408.23,1599.76 h60
  text "NONE" at 12713.96,1599.76 h60
  text "X" at 13057.46,1599.76 h60
  text "PER ORDER" at 13767.46,1599.76 h60
  text "XX MIL VIAS REQUIRE NON-CONDUCTIVE FILL AND PLANARIZE" at 11576.38,1394.82 h59
  text "XX MIL VIAS REQUIRE CONDUCTIVE FILL AND PLANARIZE" at 11584.38,1290.84 h60
  text "OUTER XX MIL TRACES REQUIRE 50 OHM SINGLE-ENDED IMPEDANCE" at 11583.39,1127.46 h58
  text "LAYER 2 & 3 (INNER LAYERS) XX MIL WIDE, XX MIL SPACE / TRACES REQUIRE 100 OHM DIFFERENTIAL IMPEDANCE" at 11575.39,891.74 h60
  text ".Layer_Name" at 577,-858.49 h60
M11 Gerber Information:
  lines w10: -292,-930.17 6308,-930.17 ; -292,-726.83 6310,-726.83 ; -292,-523.5 -292,-1133.5 3713,-1133.5 6310,-1133.5 6310,-523.5 -291.5,-523.5 -291.5,-1133.5 1284,-1133.5 ; 2173,-1133.5 2173,-523.5 ; 3440,-726.83 3440,-523.5 ; 4280,-726.83 4280,-523.5 ; 4902,-1140 4902,-937.17
  text "ALL ARTWORK VIEWED FROM TOP SIDE" at -228.5,-655.67 h60
  text "BOARD #:" at 2248,-655.67 h60
  text ".PRJ_Number" at 2793.5,-655.67 h60
  text "REV:" at 3638,-655.67 h60
  text ".PCB_Rev" at 3929.5,-655.67 h60
  text "SVN REV:" at 4476,-655.67 h60
  text ".VersionControl_RevNumber" at 4982,-655.67 h60
  text "LAYER NAME =" at -228.5,-858.49 h60
  text "TID #:" at 2248,-859 h60
  text ".TID" at 2793.5,-859 h60
  text "PLOT NAME =" at -228.5,-1064.34 h60
  text ".plot_File_Name" at 577,-1064.34 h60
  text "GENERATED    :" at 2250,-1064.34 h60
  text ".Print_Date" at 3119.5,-1064.34 h60
  text ".Print_Time" at 3848.5,-1064.34 h60
  text "TEXAS INSTRUMENTS" at 5113,-1064.34 h60
M12 Stackup:
  drawing of 191 lines, arcs and shapes, not listed
  text "Layer" at 9496.63,7601.91 h60
  text "Name" at 9906.55,7601.91 h60
  text "Material" at 10836.29,7601.91 h60
  text "Thickness" at 11696.06,7601.91 h60
  text "Constant" at 12345.89,7601.91 h60
  text "Board Layer Stack" at 12915.75,7601.91 h60
  text "1" at 9496.63,7481.91 h60
  text "Top Overlay" at 9906.55,7481.91 h60
  text "2" at 9496.63,7361.91 h60
  text "Top Solder" at 9906.55,7361.91 h60
  text "Solder Resist" at 10836.29,7361.91 h60
  text "0.40mil" at 11696.06,7361.91 h60
  text "3.5" at 12345.89,7361.91 h60
  text "3" at 9496.63,7241.91 h60
  text "Top Layer" at 9906.55,7241.91 h60
  text "Copper" at 10836.29,7241.91 h60
  text "1.40mil" at 11696.06,7241.91 h60
  text "4" at 9496.63,7121.91 h60
  text "Dielectric1" at 9906.55,7121.91 h60
  text "FR-4" at 10836.29,7121.91 h60
  text "59.20mil" at 11696.06,7121.91 h60
  text "4.8" at 12345.89,7121.91 h60
  text "5" at 9496.63,7001.91 h60
  text "Bottom Layer" at 9906.55,7001.91 h60
  text "Copper" at 10836.29,7001.91 h60
  text "1.40mil" at 11696.06,7001.91 h60
  text "6" at 9496.63,6881.91 h60
  text "Bottom Solder" at 9906.55,6881.91 h60
  text "Solder Resist" at 10836.29,6881.91 h60
  text "0.40mil" at 11696.06,6881.91 h60
  text "3.5" at 12345.89,6881.91 h60
  text "7" at 9496.63,6761.91 h60
  text "Bottom Overlay" at 9906.55,6761.91 h60
  text ".Layer_Name" at 577,-858.49 h60
M13 Component Bodies Top:
  text ".Layer_Name" at 577,-858.49 h60
M14 Component Bodies Bottom:
  text ".Layer_Name" at 577,-858.49 h60
M15 Courtyards Top:
  text ".Layer_Name" at 577,-858.49 h60
M16 Courtyards Bottom:
  text ".Layer_Name" at 577,-858.49 h60
Drill Drawing:
  lines w10: 107.27,1901.99 107.27,1915.8 121.08,1929.62 107.27,1943.43 107.27,1957.24 121.08,1957.24 134.9,1943.43 148.71,1957.24 162.52,1957.24 162.52,1943.43 148.71,1929.62 162.52,1915.8 162.52,1901.99 148.71,1901.99 134.9,1915.8 121.08,1901.99 107.27,1901.99 ; 107.27,2026.31 162.52,2026.31 162.52,2081.56 107.27,2081.56 107.27,2026.31 ; 107.27,2164.44 121.08,2164.44 134.9,2150.63 148.71,2164.44 162.52,2164.44 148.71,2178.26 162.52,2192.07 148.71,2192.07 134.9,2205.88 121.08,2192.07 107.27,2192.07 121.08,2178.26 107.27,2164.44 ; 107.27,2288.76 121.08,2288.76 121.08,2274.95 148.71,2274.95 148.71,2288.76 162.52,2288.76 162.52,2316.39 148.71,2316.39 148.71,2330.2 121.08,2330.2 121.08,2316.39 107.27,2316.39 107.27,2288.76 ; 107.27,2399.27 134.9,2413.08 162.52,2399.27 148.71,2426.9 162.52,2454.52 134.9,2440.71 107.27,2454.52 121.08,2426.9 107.27,2399.27
  lines w12: 57.18,1864.69 3288.67,1864.69 ; 57.18,2486.29 3288.67,2486.29 ; 395.04,1740.37 395.04,2610.61 ; 727.04,1740.37 727.04,2610.61 ; 1363.61,1740.37 1363.61,2610.61 ; 1622.75,1740.37 1622.75,2610.61 ; 1997.91,1740.37 1997.91,2610.61 ; 2722.24,1740.37 2722.24,2610.61 ; 57.18,1740.37 3288.67,1740.37 3288.67,2610.61 57.18,2610.61 57.18,1740.37
  text "Symbol" at 131.77,2523.59 h72
  text "Quantity" at 432.34,2523.59 h72
  text "Finished Hole Size" at 764.34,2523.59 h72
  text "Plated" at 1400.9,2523.59 h72
  text "Hole Type" at 1660.04,2523.59 h72
  text "Drill Layer Pair" at 2035.2,2523.59 h72
  text "Hole Tolerance" at 2759.53,2523.59 h72
  text "7" at 432.34,2399.27 h60
  text "7.87mil (0.200mm)" at 764.34,2399.27 h60
  text "PTH" at 1400.9,2399.27 h60
  text "Round" at 1660.04,2399.27 h60
  text "Top Layer - Bottom Layer" at 2035.2,2399.27 h60
  text "24" at 432.34,2274.95 h60
  text "12.21mil (0.310mm)" at 764.34,2274.95 h60
  text "PTH" at 1400.9,2274.95 h60
  text "Round" at 1660.04,2274.95 h60
  text "Top Layer - Bottom Layer" at 2035.2,2274.95 h60
  text "4" at 432.34,2150.63 h60
  text "25.59mil (0.650mm)" at 764.34,2150.63 h60
  text "PTH" at 1400.9,2150.63 h60
  text "Round" at 1660.04,2150.63 h60
  text "Top Layer - Bottom Layer" at 2035.2,2150.63 h60
  text "4" at 432.34,2026.31 h60
  text "31.50mil (0.800mm)" at 764.34,2026.31 h60
  text "PTH" at 1400.9,2026.31 h60
  text "Round" at 1660.04,2026.31 h60
  text "Top Layer - Bottom Layer" at 2035.2,2026.31 h60
  text "4" at 432.34,1901.99 h60
  text "51.18mil (1.300mm)" at 764.34,1901.99 h60
  text "PTH" at 1400.9,1901.99 h60
  text "Round" at 1660.04,1901.99 h60
  text "Top Layer - Bottom Layer" at 2035.2,1901.99 h60
  text "43 Total" at 432.34,1777.67 h60
  text ".Layer_Name" at 577,-858.49 h60
M17 Embedded Cavity:
  text ".Layer_Name" at 577,-858.49 h60
M18 Embedded Assembly:
  text ".Layer_Name" at 577,-858.49 h60
M19 Embedded Keepout:
  text ".Layer_Name" at 577,-858.49 h60

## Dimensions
0,-400 to 1000,-400 on M2 Board Dimensions
0,0 to 0,1181.1 on M2 Board Dimensions
0,0 to 2283.46,0 on M2 Board Dimensions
